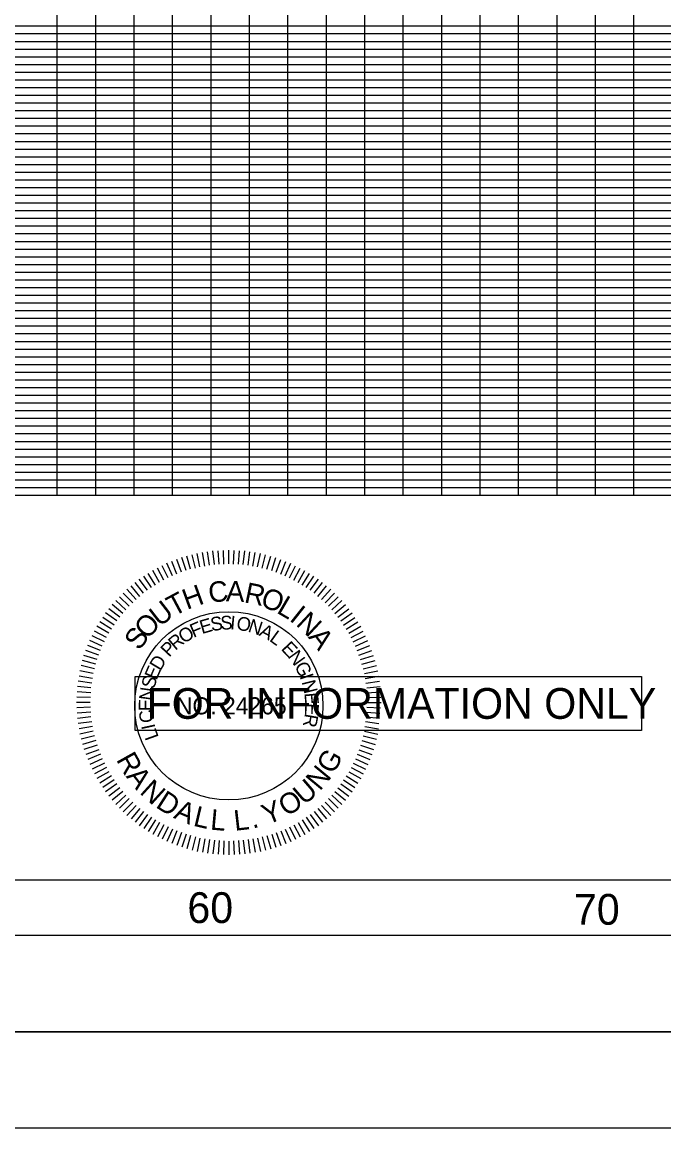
# Model space of a CAD drawing. Extents: x -15 to 165, y -6 to 109.
# Drawn here: x 135.09 to 151.78, y -6.45 to 22.3 of the extents above; entities that cross this region are included whole.
import ezdxf

# ---------------------------------------------------------------- set-up
doc = ezdxf.new("R2010")
doc.units = 0
for name, color, linetype in [('RD_SHT_Bndy', 7, 'Continuous'), ('RD_SHT_Iplotshp', 7, 'Continuous'), ('RD_SHT_MjGrid', 7, 'Continuous'), ('RD_SHT_MnGrid', 7, 'Continuous'), ('RD_SHT_SubGrid', 7, 'Continuous'), ('RD_SHT_TX', 7, 'Continuous'), ('RD_TX_PEShield', 7, 'Continuous'), ('RD_XS_TX_Notes', 7, 'Continuous')]:
    doc.layers.add(name, color=color, linetype=linetype)

msp = doc.modelspace()

# ---------------------------------------------------------------- linework, layer by layer
at = {"layer": 'RD_SHT_Bndy'}
for p, q in [((-12.73, -3.949), (163.27, -3.949)), ((-12.73, -6.449), (163.27, -6.449))]:
    msp.add_line(p, q, dxfattribs=at)
msp.add_lwpolyline([(-4.99, 103.551), (162.51, 103.551), (162.51, -1.449), (-4.99, -1.449)], close=True, dxfattribs=at)
at = {"layer": 'RD_SHT_Iplotshp'}
msp.add_lwpolyline([(-14.589, 106.051), (165.01, 106.051), (165.01, -3.949), (-14.589, -3.949)], close=True, dxfattribs=at)
at = {"layer": 'RD_SHT_MjGrid'}
for p, q in [((140, 10), (140, 100)), ((145, 10), (145, 100)), ((150, 10), (150, 100)), ((0, 20), (160, 20)), ((0, 15), (160, 15)), ((0, 10), (160, 10)), ((0, 0), (160, 0))]:
    msp.add_line(p, q, dxfattribs=at)
at = {"layer": 'RD_SHT_MnGrid'}
for p, q in [((136, 10), (136, 100)), ((137, 10), (137, 100)), ((138, 10), (138, 100)), ((139, 10), (139, 100)), ((141, 10), (141, 100)), ((142, 10), (142, 100)), ((143, 10), (143, 100)), ((144, 10), (144, 100)), ((146, 10), (146, 100)), ((147, 10), (147, 100)), ((148, 10), (148, 100)), ((149, 10), (149, 100)), ((151, 10), (151, 100)), ((0, 22), (160, 22)), ((0, 21), (160, 21)), ((0, 19), (160, 19)), ((0, 18), (160, 18)), ((0, 17), (160, 17)), ((0, 16), (160, 16)), ((0, 14), (160, 14)), ((0, 13), (160, 13)), ((0, 12), (160, 12)), ((0, 11), (160, 11))]:
    msp.add_line(p, q, dxfattribs=at)
at = {"layer": 'RD_SHT_SubGrid'}
for p, q in [((0, 22.2), (160, 22.2)), ((0, 21.8), (160, 21.8)), ((0, 21.6), (160, 21.6)), ((0, 21.4), (160, 21.4)), ((0, 21.2), (160, 21.2)), ((0, 20.8), (160, 20.8)), ((0, 20.6), (160, 20.6)), ((0, 20.4), (160, 20.4)), ((0, 20.2), (160, 20.2)), ((0, 19.8), (160, 19.8)), ((0, 19.6), (160, 19.6)), ((0, 19.4), (160, 19.4)), ((0, 19.2), (160, 19.2)), ((0, 18.8), (160, 18.8)), ((0, 18.6), (160, 18.6)), ((0, 18.4), (160, 18.4)), ((0, 18.2), (160, 18.2)), ((0, 17.8), (160, 17.8)), ((0, 17.6), (160, 17.6)), ((0, 17.4), (160, 17.4)), ((0, 17.2), (160, 17.2)), ((0, 16.8), (160, 16.8)), ((0, 16.6), (160, 16.6)), ((0, 16.4), (160, 16.4)), ((0, 16.2), (160, 16.2)), ((0, 15.8), (160, 15.8)), ((0, 15.6), (160, 15.6)), ((0, 15.4), (160, 15.4)), ((0, 15.2), (160, 15.2)), ((0, 14.8), (160, 14.8)), ((0, 14.6), (160, 14.6)), ((0, 14.4), (160, 14.4)), ((0, 14.2), (160, 14.2)), ((0, 13.8), (160, 13.8)), ((0, 13.6), (160, 13.6)), ((0, 13.4), (160, 13.4)), ((0, 13.2), (160, 13.2)), ((0, 12.8), (160, 12.8)), ((0, 12.6), (160, 12.6)), ((0, 12.4), (160, 12.4)), ((0, 12.2), (160, 12.2)), ((0, 11.8), (160, 11.8)), ((0, 11.6), (160, 11.6)), ((0, 11.4), (160, 11.4)), ((0, 11.2), (160, 11.2)), ((0, 10.8), (160, 10.8)), ((0, 10.6), (160, 10.6)), ((0, 10.4), (160, 10.4)), ((0, 10.2), (160, 10.2))]:
    msp.add_line(p, q, dxfattribs=at)
at = {"layer": 'RD_TX_PEShield'}
for p, q in [((139.349, 8.04), (139.239, 8.379)), ((139.349, 8.04), (139.239, 8.379)), ((139.47, 8.073), (139.372, 8.414)), ((139.47, 8.073), (139.372, 8.414)), ((139.592, 8.105), (139.506, 8.45)), ((139.592, 8.105), (139.506, 8.45)), ((139.713, 8.138), (139.639, 8.486)), ((139.713, 8.138), (139.639, 8.486)), ((139.838, 8.157), (139.776, 8.508)), ((139.838, 8.157), (139.776, 8.508)), ((139.962, 8.177), (139.912, 8.529)), ((139.962, 8.177), (139.912, 8.529)), ((140.086, 8.197), (140.049, 8.551)), ((140.086, 8.197), (140.049, 8.551)), ((140.212, 8.203), (140.187, 8.558)), ((140.212, 8.203), (140.187, 8.558)), ((140.337, 8.21), (140.325, 8.565)), ((140.337, 8.21), (140.325, 8.565)), ((140.463, 8.217), (140.463, 8.573)), ((140.463, 8.217), (140.463, 8.573)), ((140.588, 8.21), (140.601, 8.565)), ((140.588, 8.21), (140.601, 8.565)), ((140.714, 8.203), (140.739, 8.558)), ((140.714, 8.203), (140.739, 8.558)), ((140.84, 8.197), (140.877, 8.551)), ((140.84, 8.197), (140.877, 8.551)), ((140.964, 8.177), (141.013, 8.529)), ((140.964, 8.177), (141.013, 8.529)), ((141.088, 8.157), (141.15, 8.508)), ((141.088, 8.157), (141.15, 8.508)), ((141.212, 8.138), (141.286, 8.486)), ((141.212, 8.138), (141.286, 8.486)), ((141.212, 8.138), (141.286, 8.486)), ((141.334, 8.105), (141.42, 8.45)), ((141.334, 8.105), (141.42, 8.45)), ((141.334, 8.105), (141.42, 8.45)), ((141.455, 8.073), (141.553, 8.414)), ((141.455, 8.073), (141.553, 8.414)), ((141.455, 8.073), (141.553, 8.414)), ((141.577, 8.04), (141.687, 8.379)), ((141.577, 8.04), (141.687, 8.379)), ((141.577, 8.04), (141.687, 8.379)), ((138.773, 7.791), (138.606, 8.105)), ((138.773, 7.791), (138.606, 8.105)), ((138.885, 7.848), (138.729, 8.167)), ((138.885, 7.848), (138.729, 8.167)), ((138.997, 7.905), (138.852, 8.23)), ((138.997, 7.905), (138.852, 8.23)), ((139.114, 7.95), (138.981, 8.28)), ((139.114, 7.95), (138.981, 8.28)), ((139.231, 7.995), (139.11, 8.329)), ((139.231, 7.995), (139.11, 8.329)), ((141.694, 7.995), (141.816, 8.329)), ((141.694, 7.995), (141.816, 8.329)), ((141.694, 7.995), (141.816, 8.329)), ((141.811, 7.95), (141.945, 8.28)), ((141.811, 7.95), (141.945, 8.28)), ((141.811, 7.95), (141.945, 8.28)), ((141.929, 7.905), (142.074, 8.23)), ((141.929, 7.905), (142.074, 8.23)), ((141.929, 7.905), (142.074, 8.23)), ((142.041, 7.848), (142.197, 8.167)), ((142.041, 7.848), (142.197, 8.167)), ((142.041, 7.848), (142.197, 8.167)), ((142.153, 7.791), (142.32, 8.105)), ((142.153, 7.791), (142.32, 8.105)), ((142.153, 7.791), (142.32, 8.105)), ((138.344, 7.528), (138.135, 7.816)), ((138.344, 7.528), (138.135, 7.816)), ((138.45, 7.597), (138.251, 7.891)), ((138.45, 7.597), (138.251, 7.891)), ((138.555, 7.665), (138.367, 7.967)), ((138.555, 7.665), (138.367, 7.967)), ((138.661, 7.734), (138.483, 8.042)), ((138.661, 7.734), (138.483, 8.042)), ((142.265, 7.734), (142.443, 8.042)), ((142.265, 7.734), (142.443, 8.042)), ((142.265, 7.734), (142.443, 8.042)), ((142.371, 7.665), (142.559, 7.967)), ((142.371, 7.665), (142.559, 7.967)), ((142.371, 7.665), (142.559, 7.967)), ((142.476, 7.597), (142.675, 7.891)), ((142.476, 7.597), (142.675, 7.891)), ((142.476, 7.597), (142.675, 7.891)), ((142.581, 7.528), (142.791, 7.816)), ((142.581, 7.528), (142.791, 7.816)), ((142.581, 7.528), (142.791, 7.816)), ((138.051, 7.291), (137.813, 7.555)), ((138.051, 7.291), (137.813, 7.555)), ((138.149, 7.37), (137.92, 7.642)), ((138.149, 7.37), (137.92, 7.642)), ((138.246, 7.449), (138.027, 7.729)), ((138.246, 7.449), (138.027, 7.729)), ((142.679, 7.449), (142.898, 7.729)), ((142.679, 7.449), (142.898, 7.729)), ((142.679, 7.449), (142.898, 7.729)), ((142.777, 7.37), (143.005, 7.642)), ((142.777, 7.37), (143.005, 7.642)), ((142.777, 7.37), (143.005, 7.642)), ((142.875, 7.291), (143.113, 7.555)), ((142.875, 7.291), (143.113, 7.555)), ((142.875, 7.291), (143.113, 7.555)), ((137.784, 7.024), (137.52, 7.262)), ((137.784, 7.024), (137.52, 7.262)), ((137.873, 7.113), (137.617, 7.36)), ((137.873, 7.113), (137.617, 7.36)), ((137.962, 7.202), (137.715, 7.457)), ((137.962, 7.202), (137.715, 7.457)), ((142.964, 7.202), (143.211, 7.457)), ((142.964, 7.202), (143.211, 7.457)), ((142.964, 7.202), (143.211, 7.457)), ((143.052, 7.113), (143.308, 7.36)), ((143.052, 7.113), (143.308, 7.36)), ((143.052, 7.113), (143.308, 7.36)), ((143.141, 7.024), (143.406, 7.262)), ((143.141, 7.024), (143.406, 7.262)), ((143.141, 7.024), (143.406, 7.262)), ((137.547, 6.731), (137.259, 6.94)), ((137.547, 6.731), (137.259, 6.94)), ((137.626, 6.828), (137.346, 7.047)), ((137.626, 6.828), (137.346, 7.047)), ((137.705, 6.926), (137.433, 7.155)), ((137.705, 6.926), (137.433, 7.155)), ((143.221, 6.926), (143.493, 7.155)), ((143.221, 6.926), (143.493, 7.155)), ((143.221, 6.926), (143.493, 7.155)), ((143.3, 6.828), (143.58, 7.047)), ((143.3, 6.828), (143.58, 7.047)), ((143.3, 6.828), (143.58, 7.047)), ((143.379, 6.731), (143.667, 6.94)), ((143.379, 6.731), (143.667, 6.94)), ((143.379, 6.731), (143.667, 6.94)), ((137.41, 6.52), (137.108, 6.708)), ((137.41, 6.52), (137.108, 6.708)), ((137.478, 6.625), (137.183, 6.824)), ((137.478, 6.625), (137.183, 6.824)), ((143.447, 6.625), (143.742, 6.824)), ((143.447, 6.625), (143.742, 6.824)), ((143.447, 6.625), (143.742, 6.824)), ((143.516, 6.52), (143.817, 6.708)), ((143.516, 6.52), (143.817, 6.708)), ((143.516, 6.52), (143.817, 6.708)), ((137.227, 6.19), (136.907, 6.346)), ((137.227, 6.19), (136.907, 6.346)), ((137.284, 6.302), (136.97, 6.469)), ((137.284, 6.302), (136.97, 6.469)), ((137.341, 6.414), (137.033, 6.592)), ((137.341, 6.414), (137.033, 6.592)), ((143.584, 6.414), (143.893, 6.592)), ((143.584, 6.414), (143.893, 6.592)), ((143.584, 6.414), (143.893, 6.592)), ((143.641, 6.302), (143.955, 6.469)), ((143.641, 6.302), (143.955, 6.469)), ((143.641, 6.302), (143.955, 6.469)), ((143.699, 6.19), (144.018, 6.346)), ((143.699, 6.19), (144.018, 6.346)), ((143.699, 6.19), (144.018, 6.346)), ((137.125, 5.961), (136.795, 6.094)), ((137.125, 5.961), (136.795, 6.094)), ((137.17, 6.078), (136.845, 6.223)), ((137.17, 6.078), (136.845, 6.223)), ((143.756, 6.078), (144.081, 6.223)), ((143.756, 6.078), (144.081, 6.223)), ((143.756, 6.078), (144.081, 6.223)), ((143.801, 5.961), (144.13, 6.094)), ((143.801, 5.961), (144.13, 6.094)), ((143.801, 5.961), (144.13, 6.094)), ((137.035, 5.726), (136.696, 5.836)), ((137.035, 5.726), (136.696, 5.836)), ((137.08, 5.843), (136.746, 5.965)), ((137.08, 5.843), (136.746, 5.965)), ((143.846, 5.843), (144.18, 5.965)), ((143.846, 5.843), (144.18, 5.965)), ((143.846, 5.843), (144.18, 5.965)), ((143.891, 5.726), (144.229, 5.836)), ((143.891, 5.726), (144.229, 5.836)), ((143.891, 5.726), (144.229, 5.836)), ((136.97, 5.483), (136.625, 5.569)), ((136.97, 5.483), (136.625, 5.569)), ((137.002, 5.604), (136.66, 5.702)), ((137.002, 5.604), (136.66, 5.702)), ((143.923, 5.604), (144.265, 5.702)), ((143.923, 5.604), (144.265, 5.702)), ((143.923, 5.604), (144.265, 5.702)), ((143.956, 5.483), (144.301, 5.569)), ((143.956, 5.483), (144.301, 5.569)), ((143.956, 5.483), (144.301, 5.569)), ((136.917, 5.237), (136.567, 5.299)), ((136.917, 5.237), (136.567, 5.299)), ((136.937, 5.361), (136.589, 5.435)), ((136.937, 5.361), (136.589, 5.435)), ((143.988, 5.361), (144.337, 5.435)), ((143.988, 5.361), (144.337, 5.435)), ((143.988, 5.361), (144.337, 5.435)), ((144.008, 5.237), (144.358, 5.299)), ((144.008, 5.237), (144.358, 5.299)), ((144.008, 5.237), (144.358, 5.299)), ((136.871, 4.863), (136.517, 4.888)), ((136.871, 4.863), (136.517, 4.888)), ((136.878, 4.989), (136.524, 5.026)), ((136.878, 4.989), (136.524, 5.026)), ((136.898, 5.113), (136.546, 5.163)), ((136.898, 5.113), (136.546, 5.163)), ((144.028, 5.113), (144.38, 5.163)), ((144.028, 5.113), (144.38, 5.163)), ((144.028, 5.113), (144.38, 5.163)), ((144.048, 4.989), (144.402, 5.026)), ((144.048, 4.989), (144.402, 5.026)), ((144.048, 4.989), (144.402, 5.026)), ((144.054, 4.863), (144.409, 4.888)), ((144.054, 4.863), (144.409, 4.888)), ((144.054, 4.863), (144.409, 4.888)), ((136.858, 4.612), (136.502, 4.612)), ((136.858, 4.612), (136.502, 4.612)), ((136.865, 4.738), (136.509, 4.75)), ((136.865, 4.738), (136.509, 4.75)), ((144.061, 4.738), (144.416, 4.75)), ((144.061, 4.738), (144.416, 4.75)), ((144.061, 4.738), (144.416, 4.75)), ((144.067, 4.612), (144.423, 4.612)), ((144.067, 4.612), (144.423, 4.612)), ((144.067, 4.612), (144.423, 4.612)), ((136.865, 4.486), (136.509, 4.474)), ((136.865, 4.486), (136.509, 4.474)), ((136.871, 4.361), (136.517, 4.336)), ((136.871, 4.361), (136.517, 4.336)), ((144.041, 4.362), (144.394, 4.337)), ((144.041, 4.362), (144.394, 4.337)), ((144.054, 4.487), (144.409, 4.474)), ((144.054, 4.487), (144.409, 4.474)), ((136.878, 4.235), (136.524, 4.198)), ((136.878, 4.235), (136.524, 4.198)), ((136.898, 4.111), (136.546, 4.061)), ((136.898, 4.111), (136.546, 4.061)), ((144.015, 4.113), (144.366, 4.063)), ((144.015, 4.113), (144.366, 4.063)), ((144.028, 4.237), (144.38, 4.2)), ((144.028, 4.237), (144.38, 4.2)), ((136.917, 3.987), (136.567, 3.925)), ((136.917, 3.987), (136.567, 3.925)), ((136.937, 3.863), (136.589, 3.789)), ((136.937, 3.863), (136.589, 3.789)), ((136.97, 3.741), (136.625, 3.655)), ((136.97, 3.741), (136.625, 3.655)), ((143.956, 3.741), (144.301, 3.655)), ((143.956, 3.741), (144.301, 3.655)), ((143.988, 3.863), (144.337, 3.789)), ((143.988, 3.863), (144.337, 3.789)), ((144.002, 3.988), (144.351, 3.926)), ((144.002, 3.988), (144.351, 3.926)), ((137.002, 3.62), (136.66, 3.522)), ((137.002, 3.62), (136.66, 3.522)), ((137.035, 3.498), (136.696, 3.388)), ((143.891, 3.498), (144.229, 3.388)), ((143.891, 3.498), (144.229, 3.388)), ((143.923, 3.62), (144.265, 3.522)), ((143.923, 3.62), (144.265, 3.522)), ((137.08, 3.381), (136.746, 3.259)), ((137.08, 3.381), (136.746, 3.259)), ((137.125, 3.263), (136.795, 3.13)), ((137.125, 3.263), (136.795, 3.13)), ((143.801, 3.263), (144.13, 3.13)), ((143.801, 3.263), (144.13, 3.13)), ((143.846, 3.381), (144.18, 3.259)), ((143.846, 3.381), (144.18, 3.259)), ((137.17, 3.146), (136.845, 3.001)), ((137.17, 3.146), (136.845, 3.001)), ((137.227, 3.034), (136.907, 2.878)), ((137.227, 3.034), (136.907, 2.878)), ((137.284, 2.922), (136.97, 2.755)), ((137.284, 2.922), (136.97, 2.755)), ((143.641, 2.922), (143.955, 2.755)), ((143.641, 2.922), (143.955, 2.755)), ((143.699, 3.034), (144.018, 2.878)), ((143.699, 3.034), (144.018, 2.878)), ((143.756, 3.146), (144.081, 3.001)), ((143.756, 3.146), (144.081, 3.001)), ((137.341, 2.81), (137.033, 2.632)), ((137.341, 2.81), (137.033, 2.632)), ((137.41, 2.704), (137.108, 2.516)), ((137.41, 2.704), (137.108, 2.516)), ((137.478, 2.599), (137.183, 2.4)), ((137.478, 2.599), (137.183, 2.4)), ((143.447, 2.599), (143.742, 2.4)), ((143.447, 2.599), (143.742, 2.4)), ((143.516, 2.704), (143.817, 2.516)), ((143.516, 2.704), (143.817, 2.516)), ((143.584, 2.81), (143.893, 2.632)), ((143.584, 2.81), (143.893, 2.632)), ((137.547, 2.493), (137.259, 2.284)), ((137.547, 2.493), (137.259, 2.284)), ((137.626, 2.396), (137.346, 2.177)), ((137.626, 2.396), (137.346, 2.177)), ((143.3, 2.396), (143.58, 2.177)), ((143.3, 2.396), (143.58, 2.177)), ((143.379, 2.493), (143.667, 2.284)), ((143.379, 2.493), (143.667, 2.284)), ((137.705, 2.298), (137.433, 2.069)), ((137.705, 2.298), (137.433, 2.069)), ((137.784, 2.2), (137.52, 1.962)), ((137.784, 2.2), (137.52, 1.962)), ((137.873, 2.111), (137.617, 1.864)), ((137.873, 2.111), (137.617, 1.864)), ((137.962, 2.022), (137.715, 1.767)), ((137.962, 2.022), (137.715, 1.767)), ((142.964, 2.022), (143.211, 1.767)), ((142.964, 2.022), (143.211, 1.767)), ((143.052, 2.111), (143.308, 1.864)), ((143.052, 2.111), (143.308, 1.864)), ((143.141, 2.2), (143.406, 1.962)), ((143.141, 2.2), (143.406, 1.962)), ((143.221, 2.298), (143.493, 2.069)), ((143.221, 2.298), (143.493, 2.069)), ((138.051, 1.933), (137.813, 1.669)), ((138.051, 1.933), (137.813, 1.669)), ((138.149, 1.854), (137.92, 1.582)), ((138.149, 1.854), (137.92, 1.582)), ((138.246, 1.775), (138.027, 1.495)), ((138.246, 1.775), (138.027, 1.495)), ((142.679, 1.775), (142.898, 1.495)), ((142.679, 1.775), (142.898, 1.495)), ((142.777, 1.854), (143.005, 1.582)), ((142.777, 1.854), (143.005, 1.582)), ((142.875, 1.933), (143.113, 1.669)), ((138.344, 1.696), (138.135, 1.408)), ((138.344, 1.696), (138.135, 1.408)), ((138.45, 1.627), (138.251, 1.333)), ((138.45, 1.627), (138.251, 1.333)), ((138.555, 1.559), (138.367, 1.257)), ((138.555, 1.559), (138.367, 1.257)), ((138.661, 1.49), (138.483, 1.182)), ((138.661, 1.49), (138.483, 1.182)), ((142.265, 1.49), (142.443, 1.182)), ((142.265, 1.49), (142.443, 1.182)), ((142.371, 1.559), (142.559, 1.257)), ((142.371, 1.559), (142.559, 1.257)), ((142.476, 1.627), (142.675, 1.333)), ((142.476, 1.627), (142.675, 1.333)), ((142.581, 1.696), (142.791, 1.408)), ((142.581, 1.696), (142.791, 1.408)), ((138.773, 1.433), (138.606, 1.119)), ((138.773, 1.433), (138.606, 1.119)), ((138.885, 1.376), (138.729, 1.057)), ((138.885, 1.376), (138.729, 1.057)), ((138.997, 1.319), (138.852, 0.994)), ((138.997, 1.319), (138.852, 0.994)), ((139.114, 1.274), (138.981, 0.944)), ((139.114, 1.274), (138.981, 0.944)), ((139.231, 1.229), (139.11, 0.895)), ((139.231, 1.229), (139.11, 0.895)), ((139.349, 1.184), (139.239, 0.845)), ((139.349, 1.184), (139.239, 0.845)), ((139.47, 1.151), (139.372, 0.81)), ((139.47, 1.151), (139.372, 0.81)), ((141.455, 1.151), (141.553, 0.81)), ((141.455, 1.151), (141.553, 0.81)), ((141.577, 1.184), (141.687, 0.845)), ((141.577, 1.184), (141.687, 0.845)), ((141.694, 1.229), (141.816, 0.895)), ((141.694, 1.229), (141.816, 0.895)), ((141.811, 1.274), (141.945, 0.944)), ((141.811, 1.274), (141.945, 0.944)), ((141.929, 1.319), (142.074, 0.994)), ((141.929, 1.319), (142.074, 0.994)), ((142.041, 1.376), (142.197, 1.057)), ((142.041, 1.376), (142.197, 1.057)), ((142.153, 1.433), (142.32, 1.119)), ((142.153, 1.433), (142.32, 1.119)), ((139.592, 1.119), (139.506, 0.774)), ((139.592, 1.119), (139.506, 0.774)), ((139.713, 1.086), (139.639, 0.738)), ((139.713, 1.086), (139.639, 0.738)), ((139.838, 1.067), (139.776, 0.716)), ((139.838, 1.067), (139.776, 0.716)), ((139.962, 1.047), (139.912, 0.695)), ((139.962, 1.047), (139.912, 0.695)), ((140.086, 1.027), (140.049, 0.673)), ((140.086, 1.027), (140.049, 0.673)), ((140.212, 1.021), (140.187, 0.666)), ((140.212, 1.021), (140.187, 0.666)), ((140.337, 1.014), (140.325, 0.659)), ((140.337, 1.014), (140.325, 0.659)), ((140.463, 1.008), (140.463, 0.652)), ((140.463, 1.008), (140.463, 0.652)), ((140.588, 1.014), (140.601, 0.659)), ((140.588, 1.014), (140.601, 0.659)), ((140.714, 1.021), (140.739, 0.666)), ((140.714, 1.021), (140.739, 0.666)), ((140.84, 1.027), (140.877, 0.673)), ((140.84, 1.027), (140.877, 0.673)), ((140.964, 1.047), (141.013, 0.695)), ((140.964, 1.047), (141.013, 0.695)), ((141.088, 1.067), (141.15, 0.716)), ((141.088, 1.067), (141.15, 0.716)), ((141.212, 1.086), (141.286, 0.738)), ((141.212, 1.086), (141.286, 0.738)), ((141.334, 1.119), (141.42, 0.774)), ((141.334, 1.119), (141.42, 0.774))]:
    msp.add_line(p, q, dxfattribs=at)
msp.add_circle((140.463, 4.524), 2.448, dxfattribs=at)
at = {"layer": 'RD_XS_TX_Notes'}
msp.add_lwpolyline([(138.031, 5.286), (151.194, 5.286), (151.194, 3.886), (138.031, 3.886)], close=True, dxfattribs=at)

# ---------------------------------------------------------------- texts
at = {"layer": 'RD_SHT_TX'}
for s, p in [('60', (139.385, -1.123)), ('70', (149.438, -1.167))]:
    msp.add_text(s, height=0.8, dxfattribs=at).set_placement(p)
at = {"layer": 'RD_TX_PEShield'}
for s, height, rotation, p in [('C', 0.534, 6.8832, (139.962, 7.198)), ('A', 0.534, 357.9448, (140.384, 7.243)), ('T', 0.534, 28.0947, (139.029, 6.836)), ('H', 0.534, 19.9102, (139.372, 7.016)), ('R', 0.534, 348.267, (140.842, 7.218)), ('O', 0.534, 339.3286, (141.256, 7.126)), ('U', 0.534, 37.7726, (138.661, 6.562)), ('L', 0.534, 329.6507, (141.682, 6.956)), ('I', 0.534, 321.4663, (142.016, 6.758)), ('N', 0.534, 317.0007, (142.185, 6.63)), ('O', 0.534, 47.4504, (138.344, 6.23)), ('F', 0.356, 23.0853, (139.544, 6.29)), ('E', 0.356, 16.1843, (139.763, 6.388)), ('S', 0.356, 8.6909, (140.012, 6.463)), ('S', 0.356, 1.79, (140.248, 6.503)), ('I', 0.356, 354.889, (140.487, 6.515)), ('O', 0.356, 350.4045, (140.643, 6.507)), ('N', 0.356, 341.7029, (140.941, 6.457)), ('A', 0.356, 333.0013, (141.227, 6.362)), ('S', 0.534, 54.9027, (138.14, 5.941)), ('R', 0.356, 39.8902, (139.072, 5.949)), ('O', 0.356, 31.7869, (139.287, 6.131)), ('L', 0.356, 324.2997, (141.497, 6.225)), ('A', 0.534, 307.3229, (142.514, 6.31)), ('P', 0.356, 46.7912, (138.911, 5.771)), ('E', 0.356, 313.2251, (141.804, 5.995)), ('D', 0.356, 59.074, (138.682, 5.413)), ('N', 0.356, 305.7317, (141.984, 5.808)), ('E', 0.356, 66.5674, (138.581, 5.173)), ('G', 0.356, 297.0301, (142.161, 5.563)), ('S', 0.356, 73.4683, (138.517, 4.942)), ('I', 0.356, 288.3285, (142.299, 5.294)), ('N', 0.356, 283.8441, (142.353, 5.148)), ('N', 0.356, 82.17, (138.476, 4.643)), ('E', 0.356, 89.6633, (138.477, 4.383)), ('E', 0.356, 275.1424, (142.426, 4.855)), ('C', 0.356, 97.7667, (138.517, 4.104)), ('E', 0.356, 267.6491, (142.452, 4.596)), ('I', 0.356, 102.2511, (138.556, 3.953)), ('R', 0.356, 260.1557, (142.444, 4.336)), ('L', 0.356, 109.7445, (138.646, 3.71)), ('R', 0.534, 299.1493, (137.523, 3.127)), ('G', 0.534, 60.1113, (143.174, 2.722)), ('N', 0.534, 50.4335, (142.832, 2.292)), ('A', 0.534, 308.0877, (137.775, 2.687)), ('N', 0.534, 317.7655, (138.122, 2.261)), ('U', 0.534, 40.7556, (142.423, 1.925)), ('D', 0.534, 327.4433, (138.536, 1.9)), ('A', 0.534, 337.1212, (139.005, 1.614)), ('Y', 0.534, 21.4, (141.451, 1.422)), ('O', 0.534, 31.0778, (141.958, 1.633)), ('L', 0.534, 346.799, (139.515, 1.41)), ('L', 0.534, 354.9835, (139.968, 1.307)), ('L', 0.534, 6.5171, (140.621, 1.273)), ('.', 0.534, 14.7016, (141.082, 1.328))]:
    msp.add_text(s, height=height, rotation=rotation, dxfattribs=at).set_placement(p)
msp.add_text('NO. 24265', height=0.445, dxfattribs=at).set_placement((139.087, 4.302))
at = {"layer": 'RD_XS_TX_Notes'}
msp.add_text('FOR INFORMATION ONLY', height=0.8, dxfattribs=at).set_placement((138.325, 4.186))

doc.saveas('drawing.dxf')
